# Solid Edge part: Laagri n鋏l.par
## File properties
Author: Türk
Template: Iso Part.par
Last saved by: Türk
Revision: 8
Application: Solid Edge
Accuracy: 0,990
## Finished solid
Body 1: solid body, 3 faces, 2 edges, 0 vertices.
  Faces by surface: plane 2, cylinder 1
  Edges by curve: circle 2
Bounding box of the edges (mm): 7.500 x 40.000 x 7.500, from (-3.75, 0, -3.75) to (3.75, 40, 3.75).
Cylindrical faces by radius (mm): R3.75 x1
Planar faces by outward normal: +y 1, -y 1
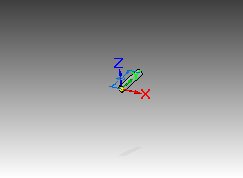
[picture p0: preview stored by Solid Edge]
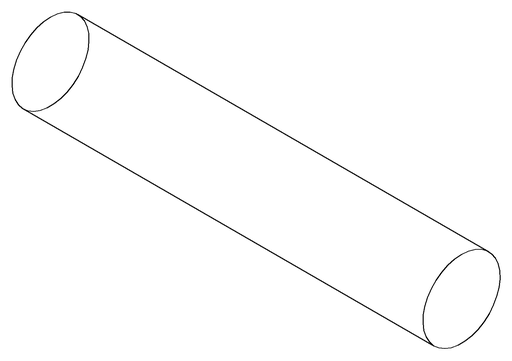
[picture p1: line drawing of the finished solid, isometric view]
